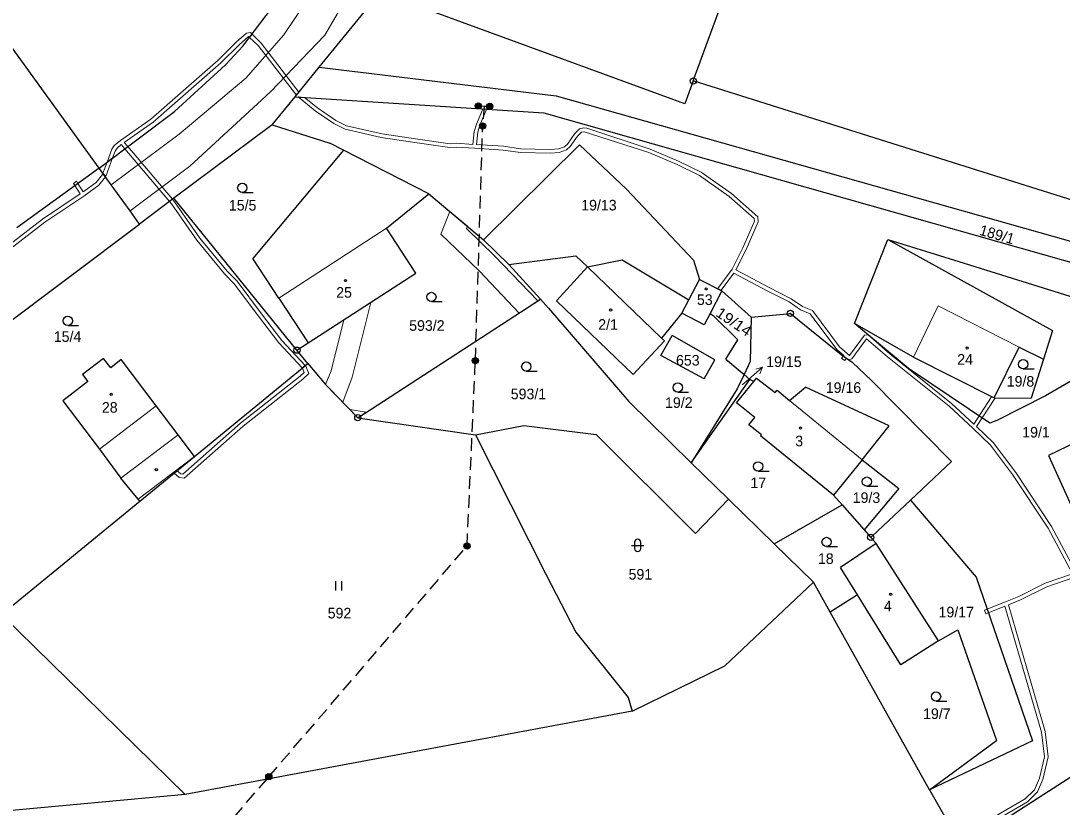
# Model space of a CAD drawing. Extents: x -653193 to -651624, y -1092017 to -1090260.
# Drawn here: x -652826.7 to -652659.4, y -1091313.6 to -1091187.1 of the extents above; entities that cross this region are included whole.
import ezdxf
from ezdxf.enums import TextEntityAlignment as Align

# ---------------------------------------------------------------- set-up
doc = ezdxf.new("R2010")
doc.units = 0
doc.header["$LTSCALE"] = 0.68
doc.linetypes.add('MEDIUM_DASHED', pattern=[4.5, 3, -1.5])
for name, color, linetype, lineweight in [('1', 7, 'Continuous', 25), ('13', 7, 'Continuous', 13), ('3', 7, 'Continuous', 25), ('4', 7, 'Continuous', 13), ('5', 7, 'Continuous', 25), ('6', 7, 'Continuous', 25), ('7', 7, 'Continuous', 13), ('8', 7, 'Continuous', 25)]:
    doc.layers.add(name, color=color, linetype=linetype, lineweight=lineweight)
doc.layers.add('2', color=7, linetype='Continuous')

msp = doc.modelspace()

# ---------------------------------------------------------------- linework, layer by layer
at = {"layer": '1'}
for p, q in [((-652718.72, -1091196.81), (-652707.84, -1091166.92)), ((-652814.18, -1091210.82), (-652837.06, -1091179.21)), ((-652778.83, -1091194.62), (-652768.98, -1091182.55)), ((-652720.05, -1091200.47), (-652768.98, -1091182.55)), ((-652791.06, -1091191.22), (-652785.43, -1091183.77)), ((-652793.86, -1091194.22), (-652791.06, -1091191.22)), ((-652802.04, -1091201.72), (-652793.86, -1091194.22)), ((-652782.69, -1091199.35), (-652778.83, -1091194.62)), ((-652778.83, -1091194.62), (-652740.73, -1091199.19)), ((-652718.72, -1091196.81), (-652720.05, -1091200.47)), ((-652651.78, -1091217.9), (-652718.72, -1091196.81)), ((-652786.35, -1091203.84), (-652782.69, -1091199.35)), ((-652782.69, -1091199.35), (-652742.73, -1091201.93)), ((-652740.73, -1091199.19), (-652652.24, -1091224.26)), ((-652814.18, -1091210.82), (-652802.04, -1091201.72)), ((-652742.73, -1091201.93), (-652653.19, -1091227.34)), ((-652786.35, -1091203.84), (-652802.15, -1091215.68)), ((-652786.35, -1091203.84), (-652777.1, -1091206.81)), ((-652774.93, -1091207.92), (-652777.1, -1091206.81)), ((-652774.93, -1091207.92), (-652789.46, -1091225.33)), ((-652761.19, -1091214.93), (-652774.93, -1091207.92)), ((-652752.42, -1091222.34), (-652736.98, -1091207.06)), ((-652736.98, -1091207.06), (-652729.42, -1091214.23)), ((-652814.18, -1091210.82), (-652827.4, -1091220.4)), ((-652812.24, -1091213.51), (-652814.18, -1091210.82)), ((-652809.2, -1091217.7), (-652812.24, -1091213.51)), ((-652768.02, -1091220.5), (-652761.19, -1091214.93)), ((-652761.19, -1091214.93), (-652752.42, -1091222.34)), ((-652729.42, -1091214.23), (-652718.66, -1091225.61)), ((-652802.15, -1091215.68), (-652807.67, -1091219.82)), ((-652782.38, -1091240.09), (-652802.15, -1091215.68)), ((-652807.67, -1091219.82), (-652809.2, -1091217.7)), ((-652834.31, -1091239.8), (-652807.67, -1091219.82)), ((-652763.3, -1091227.71), (-652768.02, -1091220.5)), ((-652752.42, -1091222.34), (-652748.37, -1091226.3)), ((-652692.82, -1091235.8), (-652687.47, -1091222.28)), ((-652687.47, -1091222.28), (-652660.99, -1091236.95)), ((-652687.47, -1091222.28), (-652676.04, -1091225.83)), ((-652748.37, -1091226.3), (-652737.59, -1091224.9)), ((-652735.71, -1091226.68), (-652737.59, -1091224.9)), ((-652785.28, -1091231.71), (-652789.46, -1091225.33)), ((-652748.37, -1091226.3), (-652743.26, -1091231.89)), ((-652735.71, -1091226.68), (-652740.7, -1091232.15)), ((-652735.71, -1091226.68), (-652730.16, -1091225.59)), ((-652730.16, -1091225.59), (-652719.44, -1091232.02)), ((-652718.66, -1091225.61), (-652717.72, -1091228.74)), ((-652676.04, -1091225.83), (-652650.37, -1091233.85)), ((-652780.59, -1091238.93), (-652763.3, -1091227.71)), ((-652719.44, -1091232.02), (-652717.72, -1091228.74)), ((-652717.72, -1091228.74), (-652714.15, -1091230.55)), ((-652785.28, -1091231.71), (-652780.59, -1091238.93)), ((-652743.26, -1091231.89), (-652741.96, -1091233.32)), ((-652714.15, -1091230.55), (-652716.02, -1091234.19)), ((-652714.15, -1091230.55), (-652709.42, -1091234.77)), ((-652741.96, -1091233.32), (-652729.05, -1091248.36)), ((-652728.38, -1091244.02), (-652740.7, -1091232.15)), ((-652720.55, -1091234.14), (-652719.44, -1091232.02)), ((-652720.55, -1091234.14), (-652723.81, -1091238.15)), ((-652716.02, -1091234.19), (-652715.51, -1091234.51)), ((-652711.54, -1091238.43), (-652715.51, -1091234.51)), ((-652709.42, -1091234.77), (-652709.56, -1091241.91)), ((-652684.12, -1091243.04), (-652692.82, -1091235.8)), ((-652683.31, -1091241.21), (-652692.82, -1091235.8)), ((-652660.99, -1091236.95), (-652662.45, -1091241.55)), ((-652723.36, -1091238.58), (-652728.38, -1091244.02)), ((-652723.92, -1091240.96), (-652722.11, -1091237.73)), ((-652723.36, -1091238.58), (-652723.81, -1091238.15)), ((-652715.24, -1091241.62), (-652722.11, -1091237.73)), ((-652713.47, -1091241.56), (-652711.54, -1091238.43)), ((-652782.38, -1091240.09), (-652780.59, -1091238.93)), ((-652780.66, -1091242.22), (-652782.38, -1091240.09)), ((-652670.36, -1091247.77), (-652666.34, -1091239.63)), ((-652666.34, -1091239.63), (-652662.45, -1091241.55)), ((-652813.44, -1091241.4), (-652816.85, -1091244.01)), ((-652812.29, -1091242.91), (-652813.44, -1091241.4)), ((-652810.65, -1091241.59), (-652812.29, -1091242.91)), ((-652804.98, -1091249.04), (-652810.65, -1091241.59)), ((-652716.95, -1091244.68), (-652723.92, -1091240.96)), ((-652716.95, -1091244.68), (-652715.24, -1091241.62)), ((-652713.47, -1091241.56), (-652710.56, -1091244.01)), ((-652709.56, -1091241.91), (-652710.56, -1091244.01)), ((-652694.94, -1091240.79), (-652693.17, -1091242.02)), ((-652683.31, -1091241.21), (-652670.36, -1091247.77)), ((-652662.45, -1091241.55), (-652664.45, -1091247.82)), ((-652798.82, -1091257.18), (-652780.66, -1091242.22)), ((-652780.66, -1091242.22), (-652777.79, -1091245.58)), ((-652693.17, -1091242.02), (-652690.08, -1091244.94)), ((-652671.09, -1091251.81), (-652684.12, -1091243.04)), ((-652654.03, -1091242.76), (-652662.13, -1091247.41)), ((-652816, -1091245.12), (-652820.01, -1091248.23)), ((-652816.85, -1091244.01), (-652816, -1091245.12)), ((-652719.03, -1091258.22), (-652709.62, -1091244.8)), ((-652711.75, -1091248.53), (-652708.98, -1091245.14)), ((-652710.56, -1091244.01), (-652711.65, -1091246.32)), ((-652710.56, -1091244.01), (-652709.62, -1091244.8)), ((-652708.98, -1091245.14), (-652709.62, -1091244.8)), ((-652708.98, -1091245.14), (-652708.55, -1091244.61)), ((-652708.55, -1091244.61), (-652705.53, -1091246.88)), ((-652690.08, -1091244.94), (-652677.24, -1091257.96)), ((-652634.48, -1091243.82), (-652661.64, -1091257.02)), ((-652711.65, -1091246.32), (-652719.03, -1091258.22)), ((-652705.53, -1091246.88), (-652705.25, -1091246.53)), ((-652705.25, -1091246.53), (-652703.25, -1091248.16)), ((-652703.25, -1091248.16), (-652700.67, -1091246.05)), ((-652687.22, -1091252.23), (-652700.67, -1091246.05)), ((-652820.01, -1091248.23), (-652814.12, -1091255.98)), ((-652729.05, -1091248.36), (-652719.03, -1091258.22)), ((-652708.83, -1091250.91), (-652711.75, -1091248.53)), ((-652670.36, -1091247.77), (-652664.45, -1091247.82)), ((-652662.13, -1091247.41), (-652669.93, -1091251.37)), ((-652801.48, -1091253.67), (-652804.98, -1091249.04)), ((-652709.77, -1091252.07), (-652708.83, -1091250.91)), ((-652669.93, -1091251.37), (-652671.09, -1091251.81)), ((-652798.82, -1091257.18), (-652801.48, -1091253.67)), ((-652753.7, -1091253.68), (-652742.32, -1091276.21)), ((-652745.95, -1091252.21), (-652734.31, -1091253.66)), ((-652734.31, -1091253.66), (-652718.37, -1091269.58)), ((-652707.77, -1091253.7), (-652709.77, -1091252.07)), ((-652691.56, -1091257.7), (-652687.22, -1091252.23)), ((-652707.89, -1091253.85), (-652707.77, -1091253.7)), ((-652696.2, -1091263.39), (-652707.89, -1091253.85)), ((-652814.12, -1091255.98), (-652810.67, -1091260.64)), ((-652661.64, -1091257.02), (-652654.35, -1091273.21)), ((-652807.65, -1091264.38), (-652798.82, -1091257.18)), ((-652719.03, -1091258.22), (-652713.06, -1091264.05)), ((-652691.56, -1091257.7), (-652696.2, -1091263.39)), ((-652691.56, -1091257.7), (-652685.67, -1091262.32)), ((-652677.24, -1091257.96), (-652683.81, -1091264.2)), ((-652807.88, -1091264.06), (-652810.67, -1091260.64)), ((-652696.2, -1091263.39), (-652694.81, -1091264.96)), ((-652685.67, -1091262.32), (-652691.25, -1091268.99)), ((-652807.65, -1091264.38), (-652807.88, -1091264.06)), ((-652718.37, -1091269.58), (-652713.06, -1091264.05)), ((-652713.06, -1091264.05), (-652705.73, -1091271.21)), ((-652705.73, -1091271.21), (-652694.81, -1091264.96)), ((-652694.81, -1091264.96), (-652691.25, -1091268.99)), ((-652683.81, -1091264.2), (-652689.97, -1091270)), ((-652683.81, -1091264.2), (-652673.25, -1091276.56)), ((-652691.25, -1091268.99), (-652690.2, -1091270.18)), ((-652689.97, -1091270), (-652690.2, -1091270.18)), ((-652690.2, -1091270.18), (-652689.32, -1091271.18)), ((-652705.73, -1091271.21), (-652699.42, -1091277.37)), ((-652689.32, -1091271.18), (-652695.07, -1091275.02)), ((-652679.29, -1091286.79), (-652689.32, -1091271.18)), ((-652692.34, -1091279.42), (-652695.07, -1091275.02)), ((-652742.32, -1091276.21), (-652737.58, -1091285.39)), ((-652673.25, -1091276.56), (-652664.21, -1091302.86)), ((-652713.62, -1091290.83), (-652699.42, -1091277.37)), ((-652696.71, -1091282.22), (-652699.42, -1091277.37)), ((-652692.34, -1091279.42), (-652696.71, -1091282.22)), ((-652685.39, -1091290.65), (-652692.34, -1091279.42)), ((-652680.76, -1091310.76), (-652696.71, -1091282.22)), ((-652675.52, -1091319.87), (-652618.24, -1091283.07)), ((-652737.58, -1091285.39), (-652729.15, -1091295.94)), ((-652679.29, -1091286.79), (-652676.19, -1091285.02)), ((-652676.19, -1091285.02), (-652670, -1091302.83)), ((-652679.29, -1091286.79), (-652685.39, -1091290.65)), ((-652728.53, -1091298.1), (-652713.62, -1091290.83)), ((-652729.15, -1091295.94), (-652728.53, -1091298.1)), ((-652728.53, -1091298.1), (-652800.34, -1091311.51)), ((-652680.76, -1091310.76), (-652670, -1091302.83)), ((-652664.21, -1091302.86), (-652680.76, -1091310.76)), ((-652800.34, -1091311.51), (-652854.02, -1091316.45)), ((-652680.76, -1091310.76), (-652675.98, -1091319.08))]:
    msp.add_line(p, q, dxfattribs=at)
for points in [[(-652777.79, -1091245.58), (-652772.61, -1091250.94), (-652743.26, -1091231.89)], [(-652716.02, -1091234.19), (-652716.96, -1091236.02), (-652720.55, -1091234.14)], [(-652709.42, -1091234.77), (-652703.11, -1091234.17), (-652694.94, -1091240.79)], [(-652772.61, -1091250.94), (-652753.7, -1091253.68), (-652745.95, -1091252.21)], [(-652800.34, -1091311.51), (-652829.87, -1091282.59), (-652807.65, -1091264.38)]]:
    msp.add_lwpolyline(points, dxfattribs=at)
at = {"layer": '13'}
for points in [[(-652812.9, -1091209.86), (-652812.01, -1091209.19), (-652811.6, -1091208.08), (-652811.28, -1091207.6), (-652810.61, -1091207.04), (-652810.04, -1091207.72), (-652809.56, -1091207.36), (-652810.13, -1091206.68), (-652805.49, -1091203.42), (-652794.62, -1091193.92), (-652791.67, -1091190.99), (-652790.19, -1091189.68), (-652790.02, -1091189.84), (-652789.58, -1091189.27), (-652789.84, -1091189.01), (-652790.47, -1091189.12), (-652792.09, -1091190.55), (-652795.02, -1091193.48), (-652805.87, -1091202.94), (-652810.75, -1091206.38), (-652811.74, -1091207.2), (-652812.14, -1091207.8)], [(-652790.02, -1091189.84), (-652788.59, -1091191.12), (-652782.47, -1091199.09), (-652782.08, -1091198.6), (-652788.13, -1091190.72), (-652789.58, -1091189.27)], [(-652810.04, -1091207.72), (-652802.85, -1091216.2), (-652802.36, -1091215.84), (-652809.56, -1091207.36)], [(-652812.9, -1091209.86), (-652813.57, -1091211.66), (-652813.1, -1091212.15), (-652812.01, -1091209.19)], [(-652818.31, -1091213.27), (-652818.07, -1091213.64), (-652817.58, -1091213.28), (-652817.82, -1091212.9)], [(-652788.55, -1091234.6), (-652785.3, -1091238.93), (-652781.52, -1091242.93), (-652781.06, -1091242.55), (-652784.84, -1091238.55), (-652788.07, -1091234.24), (-652791.99, -1091229.02), (-652793.58, -1091227.4), (-652797.97, -1091222.06), (-652802.04, -1091216.22), (-652802.36, -1091215.84), (-652802.85, -1091216.2), (-652802.52, -1091216.59), (-652798.45, -1091222.42), (-652794.02, -1091227.8), (-652792.45, -1091229.42)], [(-652746.68, -1091234.12), (-652743.7, -1091232.18), (-652750.63, -1091224.9), (-652755.15, -1091220.54), (-652755, -1091220.16), (-652757.83, -1091217.77), (-652759.25, -1091221.44), (-652753.11, -1091227.36)], [(-652773.53, -1091244.41), (-652770.52, -1091232.4), (-652774.83, -1091235.19), (-652776.89, -1091243.39), (-652777.79, -1091245.58), (-652775, -1091248.46)], [(-652801.62, -1091259.47), (-652802.09, -1091259.85), (-652801.31, -1091260.57), (-652800.53, -1091260.65), (-652791.05, -1091252.28), (-652781.45, -1091244.75), (-652780.5, -1091243.82), (-652780.95, -1091242.67), (-652781.06, -1091242.55), (-652781.52, -1091242.93), (-652781.47, -1091242.99), (-652781.2, -1091243.66), (-652781.85, -1091244.29), (-652791.43, -1091251.82), (-652800.73, -1091260.03), (-652801.05, -1091259.99)], [(-652772.61, -1091250.94), (-652771.26, -1091250.06), (-652773.89, -1091249.61)]]:
    msp.add_lwpolyline(points, close=True, dxfattribs=at)
for points in [[(-652712.59, -1091214.89), (-652717.42, -1091211.47), (-652721.08, -1091209.69), (-652725.62, -1091207.77), (-652735.82, -1091204.42), (-652736.28, -1091204.37), (-652736.98, -1091204.53), (-652737.76, -1091205.27), (-652738.94, -1091206.95), (-652739.42, -1091207.39), (-652740.39, -1091207.72), (-652741.7, -1091207.82), (-652746.45, -1091207.7), (-652749.21, -1091207.32), (-652753.52, -1091207.05), (-652753.32, -1091205.05), (-652752.98, -1091203.94), (-652751.96, -1091201.52), (-652751.99, -1091201.33), (-652752.6, -1091201.29), (-652752.58, -1091201.44), (-652753.54, -1091203.74), (-652753.92, -1091204.93), (-652754.12, -1091207.01), (-652756.74, -1091206.83), (-652757.79, -1091206.91), (-652763.35, -1091206.1), (-652768.71, -1091205.32), (-652774.42, -1091204), (-652776.15, -1091203.15), (-652779.09, -1091201.12), (-652781.15, -1091199.45), (-652782.19, -1091199.38), (-652779.45, -1091201.6), (-652776.45, -1091203.67), (-652774.62, -1091204.56), (-652768.83, -1091205.92), (-652763.43, -1091206.7), (-652757.81, -1091207.51), (-652756.74, -1091207.43), (-652753.87, -1091207.63), (-652749.27, -1091207.92), (-652746.49, -1091208.3), (-652741.68, -1091208.42), (-652740.27, -1091208.32), (-652739.1, -1091207.91), (-652738.48, -1091207.35), (-652737.3, -1091205.67), (-652736.68, -1091205.07), (-652736.24, -1091204.97), (-652725.84, -1091208.33), (-652721.32, -1091210.23), (-652717.72, -1091211.99), (-652712.97, -1091215.37), (-652708.92, -1091218.94), (-652708.89, -1091219.35), (-652710.73, -1091223.64), (-652712.48, -1091227.07), (-652714.75, -1091230.18), (-652714.21, -1091230.46), (-652712.18, -1091227.69), (-652706.82, -1091230.55), (-652703.29, -1091232.34), (-652701.47, -1091233.6), (-652699.93, -1091234.23), (-652695.65, -1091239.96), (-652694.55, -1091240.94), (-652694.88, -1091241.41), (-652694.37, -1091241.76), (-652694.17, -1091241.45), (-652693.78, -1091241.62), (-652693.26, -1091241.48), (-652690.86, -1091238.24), (-652687.53, -1091241.14), (-652677.6, -1091249.11), (-652673.8, -1091252.64), (-652670.97, -1091255.34), (-652667.41, -1091260.07), (-652661.68, -1091268.72), (-652657.77, -1091276.05), (-652662.16, -1091277.55), (-652666.39, -1091279.66), (-652668.56, -1091280.56), (-652671.9, -1091281.9), (-652671.73, -1091282.47), (-652668.64, -1091281.24), (-652662.78, -1091301.48), (-652662.27, -1091305.44), (-652663.11, -1091308.89), (-652663.91, -1091310.76), (-652665.38, -1091312.2), (-652675.79, -1091318.27)], [(-652835.95, -1091229.57), (-652822.91, -1091219.53), (-652816.65, -1091215.31), (-652814.23, -1091213.58), (-652813.16, -1091212.23), (-652813.57, -1091211.66), (-652813.64, -1091211.85), (-652814.65, -1091213.14), (-652816.73, -1091214.63), (-652817.58, -1091213.28), (-652818.07, -1091213.64), (-652817.22, -1091214.97), (-652823.27, -1091219.05), (-652836.27, -1091229.05)], [(-652657.2, -1091275.85), (-652661.16, -1091268.42), (-652666.91, -1091259.73), (-652670.53, -1091254.94), (-652673.2, -1091252.38), (-652670.25, -1091247.85), (-652670.37, -1091247.79), (-652670.79, -1091247.58), (-652673.65, -1091251.96), (-652677.2, -1091248.65), (-652687.15, -1091240.68), (-652690.64, -1091237.62), (-652691.18, -1091237.66), (-652693.62, -1091240.96), (-652695.21, -1091239.56), (-652699.55, -1091233.73), (-652701.19, -1091233.06), (-652702.99, -1091231.82), (-652706.54, -1091230.01), (-652711.86, -1091227.18), (-652710.19, -1091223.9), (-652708.29, -1091219.45), (-652708.34, -1091218.66), (-652712.59, -1091214.89)], [(-652663.41, -1091311.1), (-652662.53, -1091309.09), (-652661.67, -1091305.48), (-652662.2, -1091301.36), (-652668.08, -1091281.01), (-652666.15, -1091280.2), (-652661.92, -1091278.11), (-652657.42, -1091276.56)], [(-652675.25, -1091318.65), (-652665.02, -1091312.68), (-652663.41, -1091311.1)]]:
    msp.add_lwpolyline(points, dxfattribs=at)
at = {"layer": '3'}
for p, q in [((-652791.163, -1091214.76), (-652789.413, -1091214.76)), ((-652760.793, -1091232.29), (-652759.043, -1091232.29)), ((-652819.213, -1091236.12), (-652817.463, -1091236.12)), ((-652745.533, -1091243.47), (-652743.783, -1091243.47)), ((-652665.713, -1091243.09), (-652663.963, -1091243.09)), ((-652721.203, -1091246.84), (-652719.453, -1091246.84)), ((-652708.293, -1091259.53), (-652706.543, -1091259.53)), ((-652690.823, -1091261.97), (-652689.073, -1091261.97)), ((-652728.651, -1091271.461), (-652726.649, -1091271.461)), ((-652728.151, -1091270.961), (-652728.151, -1091271.962)), ((-652727.149, -1091271.962), (-652727.149, -1091270.961)), ((-652697.283, -1091271.67), (-652695.533, -1091271.67)), ((-652776.151, -1091278.72), (-652776.151, -1091277.22)), ((-652775.15, -1091278.72), (-652775.15, -1091277.22)), ((-652679.713, -1091296.51), (-652677.963, -1091296.51))]:
    msp.add_line(p, q, dxfattribs=at)
for centre in [(-652791.1629, -1091214.0098), (-652760.7929, -1091231.5398), (-652819.2129, -1091235.3698), (-652745.5329, -1091242.7198), (-652665.7129, -1091242.3398), (-652721.2029, -1091246.0898), (-652708.2929, -1091258.7798), (-652690.8229, -1091261.2198), (-652697.2829, -1091270.9198), (-652679.7129, -1091295.7598)]:
    msp.add_circle(centre, 0.75, dxfattribs=at)
for centre, start, end in [((-652727.65, -1091270.9609), 0, 180), ((-652727.65, -1091271.9609), 180, 359.98789)]:
    msp.add_arc(centre, 0.5, start, end, dxfattribs=at)
at = {"layer": '4'}
for p, q in [((-652777.88, -1091189.45), (-652772.06, -1091179.4)), ((-652779.87, -1091182.48), (-652784.51, -1091189.41)), ((-652784.51, -1091189.41), (-652790.59, -1091196.39)), ((-652786.63, -1091198.58), (-652777.88, -1091189.45)), ((-652790.59, -1091196.39), (-652801.29, -1091205.35)), ((-652799.57, -1091210.49), (-652786.63, -1091198.58)), ((-652801.29, -1091205.35), (-652812.24, -1091213.51)), ((-652809.2, -1091217.7), (-652799.57, -1091210.49)), ((-652768.02, -1091220.5), (-652785.28, -1091231.71)), ((-652723.81, -1091238.15), (-652735.71, -1091226.68)), ((-652679.39, -1091232.96), (-652683.31, -1091241.21)), ((-652666.34, -1091239.63), (-652679.39, -1091232.96)), ((-652703.25, -1091248.16), (-652691.56, -1091257.7)), ((-652814.12, -1091255.98), (-652804.98, -1091249.04)), ((-652810.67, -1091260.64), (-652801.48, -1091253.67)), ((-652807.88, -1091264.06), (-652798.82, -1091257.18))]:
    msp.add_line(p, q, dxfattribs=at)
at = {"layer": '5'}
for centre in [(-652774.5868, -1091228.8992), (-652716.6468, -1091230.2392), (-652731.9968, -1091233.6392), (-652674.7168, -1091239.7392), (-652812.2268, -1091247.1992), (-652701.4768, -1091252.6092), (-652804.9768, -1091259.2992), (-652687.0068, -1091279.3192)]:
    msp.add_circle(centre, 0.175, dxfattribs=at)
at = {"layer": '6', "linetype": 'MEDIUM_DASHED'}
for p, q in [((-652753.26, -1091200.82), (-652752.33, -1091200.85)), ((-652752.33, -1091200.85), (-652752.54, -1091204.05)), ((-652752.33, -1091200.85), (-652751.4, -1091200.88)), ((-652753.72, -1091241.76), (-652752.54, -1091204.05)), ((-652755.05, -1091271.57), (-652753.72, -1091241.76)), ((-652786.9, -1091308.66), (-652755.05, -1091271.57)), ((-652818.4, -1091345.29), (-652786.9, -1091308.66))]:
    msp.add_line(p, q, dxfattribs=at)
at = {"layer": '6'}
for centre, radius in [((-652753.2634, -1091200.8199), 0.5), ((-652753.2634, -1091200.8199), 0.4), ((-652753.2634, -1091200.8199), 0.3), ((-652753.2634, -1091200.8199), 0.2), ((-652753.2634, -1091200.8199), 0.1), ((-652751.4034, -1091200.8799), 0.5), ((-652751.4034, -1091200.8799), 0.4), ((-652751.4034, -1091200.8799), 0.3), ((-652751.4034, -1091200.8799), 0.2), ((-652751.4034, -1091200.8799), 0.1), ((-652752.5434, -1091204.0499), 0.5), ((-652752.5434, -1091204.0499), 0.4), ((-652752.5434, -1091204.0499), 0.3), ((-652752.5434, -1091204.0499), 0.2), ((-652752.5434, -1091204.0499), 0.1), ((-652753.7234, -1091241.7599), 0.5), ((-652753.7234, -1091241.7599), 0.4), ((-652753.7234, -1091241.7599), 0.3), ((-652753.7234, -1091241.7599), 0.2), ((-652753.7234, -1091241.7599), 0.1), ((-652755.0534, -1091271.5699), 0.5), ((-652755.0534, -1091271.5699), 0.4), ((-652755.0534, -1091271.5699), 0.3), ((-652755.0534, -1091271.5699), 0.2), ((-652755.0534, -1091271.5699), 0.1), ((-652786.9034, -1091308.6599), 0.5), ((-652786.9034, -1091308.6599), 0.4), ((-652786.9034, -1091308.6599), 0.3), ((-652786.9034, -1091308.6599), 0.2), ((-652786.9034, -1091308.6599), 0.1)]:
    msp.add_circle(centre, radius, dxfattribs=at)
at = {"layer": '7'}
msp.add_line((-652707.575, -1091242.841), (-652708.659, -1091243.12), dxfattribs=at)
msp.add_lwpolyline([(-652710.84, -1091245.67), (-652709.84, -1091244.81), (-652707.575, -1091242.841), (-652708.002, -1091243.876)], dxfattribs=at)
at = {"layer": '8'}
for centre, radius in [((-652718.72, -1091196.8099), 0.5), ((-652718.72, -1091196.8099), 0.0303), ((-652703.11, -1091234.1699), 0.5), ((-652703.11, -1091234.1699), 0.0303), ((-652782.38, -1091240.0899), 0.5), ((-652782.38, -1091240.0899), 0.0303), ((-652772.61, -1091250.9399), 0.5), ((-652772.61, -1091250.9399), 0.0303), ((-652690.2, -1091270.1799), 0.5), ((-652690.2, -1091270.1799), 0.0303)]:
    msp.add_circle(centre, radius, dxfattribs=at)

# ---------------------------------------------------------------- texts
at = {"layer": '2'}
for s, p in [('15/5', (-652791.109, -1091217.645)), ('19/13', (-652733.87, -1091217.625)), ('25', (-652774.819, -1091231.655)), ('53', (-652716.859, -1091232.815)), ('593/2', (-652761.51, -1091236.975)), ('2/1', (-652732.4, -1091236.805)), ('15/4', (-652819.239, -1091238.755)), ('653', (-652719.589, -1091242.565)), ('24', (-652675.039, -1091242.415)), ('19/16', (-652694.58, -1091246.955)), ('19/8', (-652666.139, -1091245.945)), ('593/1', (-652745.19, -1091247.975)), ('28', (-652812.459, -1091250.135)), ('19/2', (-652721.039, -1091249.375)), ('19/1', (-652663.649, -1091254.125)), ('3', (-652701.7, -1091255.535)), ('17', (-652708.269, -1091262.265)), ('19/3', (-652690.889, -1091264.645)), ('18', (-652697.419, -1091274.445)), ('591', (-652727.209, -1091276.965)), ('4', (-652687.46, -1091282.055)), ('592', (-652775.549, -1091283.205)), ('19/17', (-652676.46, -1091283.035)), ('19/7', (-652679.579, -1091299.375))]:
    msp.add_text(s, height=1.7, dxfattribs=at).set_placement(p, align=Align.CENTER)
msp.add_text('189/1', height=1.7, rotation=344, dxfattribs=at).set_placement((-652670.1378, -1091222.3019), align=Align.CENTER)
at = {"layer": '2', "width": 1.1}
msp.add_text('19/14', height=1.7, rotation=326, dxfattribs=at).set_placement((-652712.6648, -1091236.2351), align=Align.CENTER)
at = {"layer": '2'}
msp.add_text('19/15', height=1.7, dxfattribs=at).set_placement((-652706.99, -1091242.795))

doc.saveas('drawing.dxf')
